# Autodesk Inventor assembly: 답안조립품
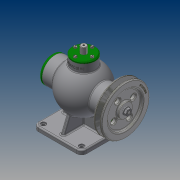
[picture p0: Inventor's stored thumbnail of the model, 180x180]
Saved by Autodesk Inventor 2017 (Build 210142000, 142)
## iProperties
Part Number: 답안조립품
Material: 일반
Document SubType Name: Assembly
Designer: 19
Author: 19
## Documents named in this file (19)
- C:\Users\19\Desktop\480414V1005\답안조립품.iam
- C:\Users\19\Desktop\480414V1005\본체.ipt
- C:\Users\19\Desktop\480414V1005\뒤커버.ipt
- C:\Users\19\Desktop\480414V1005\상부커버.ipt
- C:\Users\19\Desktop\480414V1005\앞커버.ipt
- C:\Users\19\Desktop\480414V1005\베어링 6202.ipt
- 베어링 6202.ipt
- C:\Users\19\Desktop\480414V1005\편심축.ipt
- C:\Users\19\Desktop\480414V1005\멈춤링 15x1.ipt
- C:\Users\19\Desktop\480414V1005\부시.ipt
- C:\Users\19\Desktop\480414V1005\키 4x4x12.ipt
- C:\Users\19\Desktop\480414V1005\멈춤링 35x1.6.ipt
- 멈춤링 35x1.6.ipt
- C:\Users\19\Desktop\480414V1005\오일 실 15 30 7.ipt
- C:\Users\19\Desktop\480414V1005\V-벨트풀리.ipt
- C:\Users\19\Desktop\480414V1005\너트 M8.ipt
- C:\Users\19\Desktop\480414V1005\볼트 M4x16.ipt
- C:\Users\19\Desktop\480414V1005\볼트 M4x12.ipt
- C:\Users\19\Desktop\480414V1005\슬라이드.ipt
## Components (1 placed, 1 different names)
1. V-벨트풀리:1 — 플러쉬:1
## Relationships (1: Flush 1)
- 플러쉬:1 [Flush]: V-벨트풀리:1
